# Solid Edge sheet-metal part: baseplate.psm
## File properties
Title: BasePlate
Author: ptcarter
Template: Normal.psm
Last saved by: ptcarter
Revision: 23
Application: Solid Edge
Accuracy: 0.99
Material Thickness: 2.00 mm
Bend Radius: 1.00 mm
Relief Width: 3.00 mm
Relief Length: 3.00 mm
Neutral Factor: 0.33
Minimum Arc Length: 0.10 mm
Deviational Tolerance: 0.10 mm
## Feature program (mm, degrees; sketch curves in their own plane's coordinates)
base contour flange "ContourFlange_1"
sketch for "Hole_1" plane through (-91.5, 19, 0) normal (0, -1, 0) x-axis (1, 0, 0)
  hole centre (0, -40) bore radius 3.175
hole "Hole_1"
sketch for "unnamed Hole 1" plane through (-91.5, 19, 0) normal (0, -1, 0) x-axis (1, 0, 0)
hole "unnamed Hole 1"
pattern "unnamed Pattern 1" of "Hole_1", "unnamed Hole 1"
mirror "unnamed Mirror 1" of "unnamed Pattern 1" about plane through (0, 0, 0) normal (1, 0, 0)
hole "unnamed Hole 2"
hole "unnamed Hole 3"
sketch for "Hole_5" plane through (0, -2, 0) normal (0, -1, 0) x-axis (1, 0, 0)
  hole centre (65, 0) bore radius 2.5
hole "Hole_5"
sketch for "unnamed Hole 4" plane through (0, -2, 0) normal (0, -1, 0) x-axis (1, 0, 0)
  hole centre (-65, 0) bore radius 2.5
hole "unnamed Hole 4"
pattern "unnamed Pattern 2" of "Hole_5", "unnamed Hole 4"
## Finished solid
Body 1: solid body, 28 faces, 72 edges, 40 vertices.
  Faces by surface: cylinder 14, plane 14
  Edges by curve: line 44, circle 28
Bounding box of the edges (mm): 200.000 x 23.000 x 100.000, from (-100, -2, -50) to (100, 21, 50).
Cylindrical faces by radius (mm): R1 x4, R2.5 x2, R3 x4, R3.175 x4
Planar faces by outward normal: +x 3, +y 3, +z 1, -x 3, -y 3, -z 1
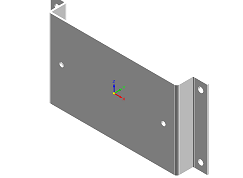
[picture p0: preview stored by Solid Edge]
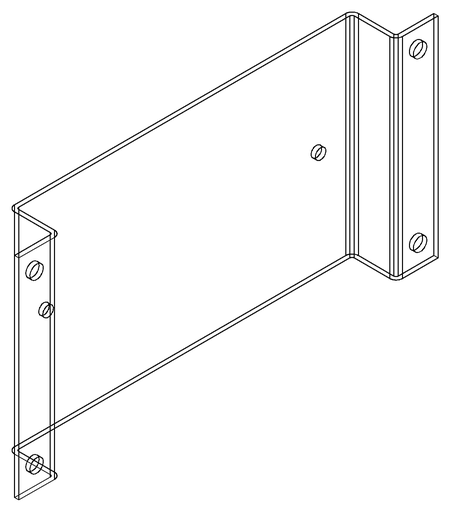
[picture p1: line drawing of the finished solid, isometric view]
